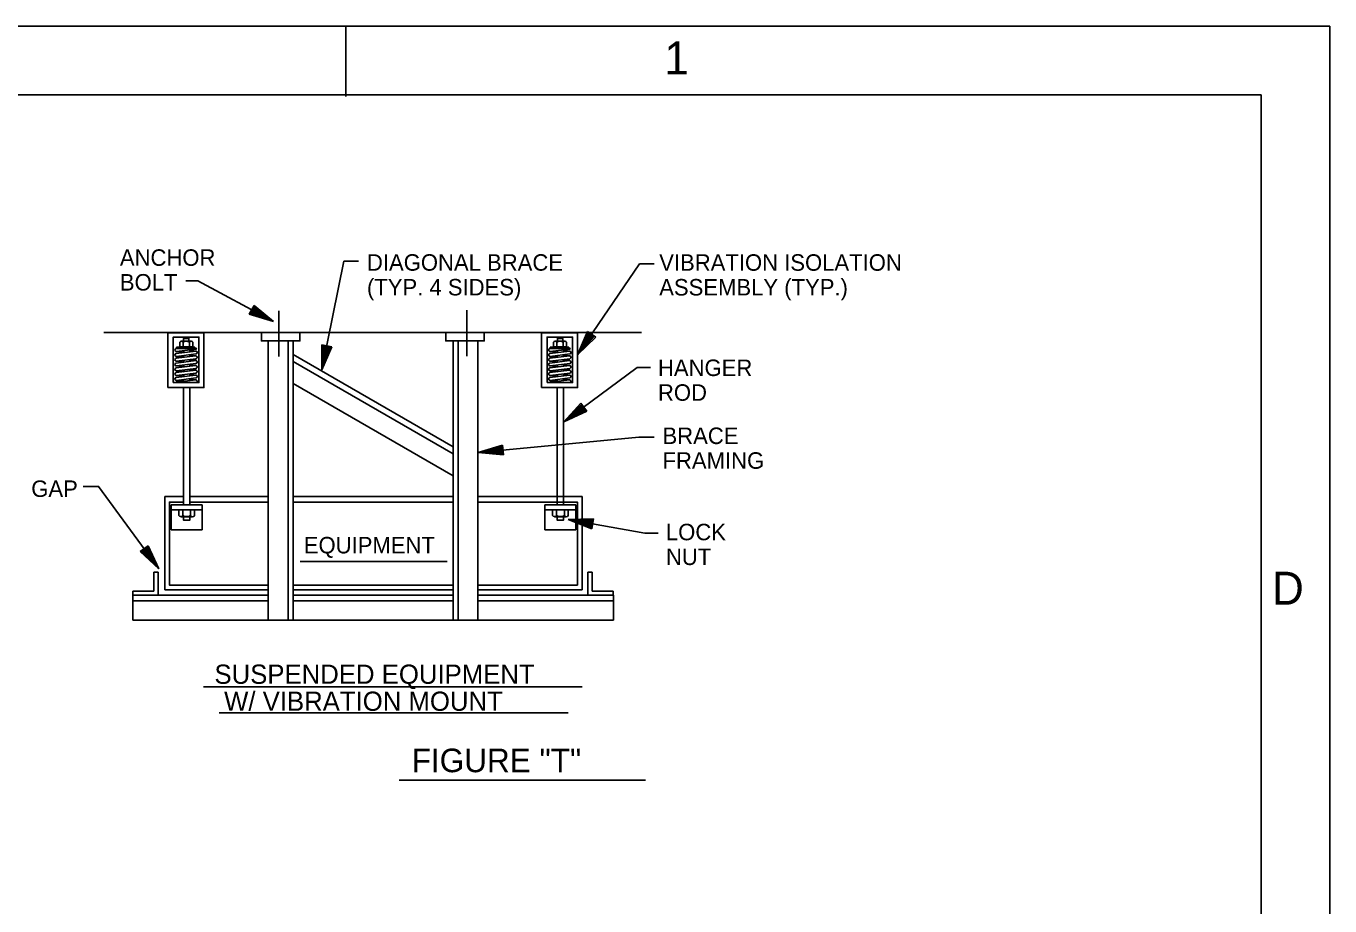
# Model space of a CAD drawing. Extents: x 10040.55 to 10045.84, y 10033.26 to 10035.76.
# Drawn here: x 10043.256 to 10044.047, y 10035.222 to 10035.756 of the extents above; entities that cross this region are included whole.
import ezdxf

# ---------------------------------------------------------------- set-up
doc = ezdxf.new("R2010")
doc.units = 0
doc.layers.add('Level 1', color=7, linetype='Continuous')
doc.layers.add('Level 2', color=7, linetype='Continuous')

msp = doc.modelspace()

# ---------------------------------------------------------------- linework, layer by layer
at = {"layer": 'Level 1'}
for p, q in [((10040.54697, 10035.75552), (10044.04697, 10035.75552)), ((10043.45014, 10035.75552), (10043.45014, 10035.71285)), ((10044.04697, 10035.75552), (10044.04697, 10033.25552)), ((10040.71364, 10035.71385), (10044.0053, 10035.71385)), ((10044.0053, 10035.71385), (10044.0053, 10033.29719))]:
    msp.add_line(p, q, dxfattribs=at)
at = {"layer": 'Level 2'}
for p, q in [((10043.39166, 10035.5808), (10043.39453, 10035.5861)), ((10043.40633, 10035.5763), (10043.39202, 10035.58148)), ((10043.40633, 10035.5763), (10043.39241, 10035.58223)), ((10043.40633, 10035.5763), (10043.39274, 10035.58281)), ((10043.39306, 10035.58344), (10043.40633, 10035.5763)), ((10043.40633, 10035.5763), (10043.39343, 10035.58409)), ((10043.40633, 10035.5763), (10043.39377, 10035.58476)), ((10043.40633, 10035.5763), (10043.39413, 10035.58539)), ((10043.39453, 10035.5861), (10043.40633, 10035.5763)), ((10043.40955, 10035.55517), (10043.40955, 10035.58292)), ((10043.52365, 10035.55543), (10043.52365, 10035.58318)), ((10043.39166, 10035.5808), (10043.40633, 10035.5763)), ((10043.3035, 10035.5696), (10043.62956, 10035.5696)), ((10043.59674, 10035.57034), (10043.59074, 10035.55622)), ((10043.59074, 10035.55622), (10043.59738, 10035.56992)), ((10043.59074, 10035.55622), (10043.59808, 10035.56946)), ((10043.59074, 10035.55622), (10043.59863, 10035.56906)), ((10043.59921, 10035.56868), (10043.59074, 10035.55622)), ((10043.59074, 10035.55622), (10043.59983, 10035.56824)), ((10043.59074, 10035.55622), (10043.60045, 10035.56783)), ((10043.59074, 10035.55622), (10043.60104, 10035.56742)), ((10043.60172, 10035.56694), (10043.59074, 10035.55622)), ((10043.59674, 10035.57034), (10043.60172, 10035.56694)), ((10043.3473, 10035.55992), (10043.35985, 10035.55992)), ((10043.35192, 10035.55756), (10043.3473, 10035.55814)), ((10043.34731, 10035.557), (10043.35915, 10035.55846)), ((10043.34748, 10035.55814), (10043.35931, 10035.55958)), ((10043.35873, 10035.56074), (10043.34754, 10035.56074)), ((10043.34754, 10035.56074), (10043.34754, 10035.55992)), ((10043.3495, 10035.56109), (10043.3495, 10035.56384)), ((10043.3495, 10035.56109), (10043.3574, 10035.56109)), ((10043.35049, 10035.56444), (10043.35641, 10035.56444)), ((10043.35146, 10035.56109), (10043.35146, 10035.56384)), ((10043.3517, 10035.55866), (10043.3517, 10035.55755)), ((10043.35543, 10035.56109), (10043.35543, 10035.56384)), ((10043.35563, 10035.55914), (10043.35563, 10035.55801)), ((10043.35563, 10035.55891), (10043.35923, 10035.55847)), ((10043.3574, 10035.56109), (10043.3574, 10035.56382)), ((10043.35873, 10035.56074), (10043.35873, 10035.55992)), ((10043.40316, 10035.39529), (10043.40316, 10035.56457)), ((10043.41522, 10035.56457), (10043.41522, 10035.39529)), ((10043.41826, 10035.39529), (10043.41826, 10035.56457)), ((10043.43575, 10035.5623), (10043.4357, 10035.54695)), ((10043.4357, 10035.54695), (10043.4365, 10035.56215)), ((10043.4357, 10035.54695), (10043.43733, 10035.562)), ((10043.4357, 10035.54695), (10043.43799, 10035.56184)), ((10043.43868, 10035.56172), (10043.4357, 10035.54695)), ((10043.4357, 10035.54695), (10043.43942, 10035.56155)), ((10043.4357, 10035.54695), (10043.44015, 10035.56142)), ((10043.4357, 10035.54695), (10043.44085, 10035.56126)), ((10043.44166, 10035.56109), (10043.4357, 10035.54695)), ((10043.43575, 10035.5623), (10043.44166, 10035.56109)), ((10043.51526, 10035.56457), (10043.51526, 10035.39529)), ((10043.51829, 10035.39529), (10043.51829, 10035.56457)), ((10043.53035, 10035.56457), (10043.53035, 10035.39529)), ((10043.57395, 10035.55992), (10043.5865, 10035.55992)), ((10043.57856, 10035.55756), (10043.57395, 10035.55814)), ((10043.57396, 10035.557), (10043.58579, 10035.55846)), ((10043.57413, 10035.55814), (10043.58596, 10035.55958)), ((10043.58538, 10035.56074), (10043.57419, 10035.56074)), ((10043.57419, 10035.56074), (10043.57419, 10035.55992)), ((10043.57615, 10035.56109), (10043.57615, 10035.56384)), ((10043.57615, 10035.56109), (10043.58404, 10035.56109)), ((10043.57714, 10035.56444), (10043.58305, 10035.56444)), ((10043.5781, 10035.56109), (10043.5781, 10035.56384)), ((10043.57834, 10035.55866), (10043.57834, 10035.55755)), ((10043.58207, 10035.56109), (10043.58207, 10035.56384)), ((10043.58227, 10035.55914), (10043.58227, 10035.55801)), ((10043.58227, 10035.55891), (10043.58588, 10035.55847)), ((10043.58404, 10035.56109), (10043.58404, 10035.56382)), ((10043.58538, 10035.56074), (10043.58538, 10035.55992)), ((10043.3473, 10035.55409), (10043.35914, 10035.55554)), ((10043.35192, 10035.55174), (10043.3473, 10035.55231)), ((10043.34731, 10035.55119), (10043.35915, 10035.55263)), ((10043.35192, 10035.55467), (10043.34732, 10035.55521)), ((10043.34748, 10035.55232), (10043.35931, 10035.55376)), ((10043.34749, 10035.55522), (10043.35932, 10035.55668)), ((10043.34749, 10035.54941), (10043.35932, 10035.55085)), ((10043.3517, 10035.55575), (10043.3517, 10035.55463)), ((10043.3517, 10035.55285), (10043.3517, 10035.55173)), ((10043.3517, 10035.54996), (10043.3517, 10035.5488)), ((10043.35563, 10035.55627), (10043.35563, 10035.55515)), ((10043.35933, 10035.55554), (10043.35563, 10035.556)), ((10043.35563, 10035.55334), (10043.35563, 10035.55218)), ((10043.35931, 10035.55263), (10043.35563, 10035.55308)), ((10043.35563, 10035.55041), (10043.35563, 10035.54928)), ((10043.35933, 10035.54972), (10043.35563, 10035.55018)), ((10043.51526, 10035.50028), (10043.41826, 10035.55628)), ((10043.41826, 10035.55219), (10043.51526, 10035.49619)), ((10043.57395, 10035.55409), (10043.58578, 10035.55554)), ((10043.57856, 10035.55174), (10043.57395, 10035.55231)), ((10043.57396, 10035.55119), (10043.58579, 10035.55263)), ((10043.57856, 10035.55467), (10043.57397, 10035.55521)), ((10043.57413, 10035.55232), (10043.58596, 10035.55376)), ((10043.57414, 10035.55522), (10043.58597, 10035.55668)), ((10043.57414, 10035.54941), (10043.58597, 10035.55085)), ((10043.57834, 10035.55575), (10043.57834, 10035.55463)), ((10043.57834, 10035.55285), (10043.57834, 10035.55173)), ((10043.57834, 10035.54996), (10043.57834, 10035.5488)), ((10043.58227, 10035.55627), (10043.58227, 10035.55515)), ((10043.58598, 10035.55554), (10043.58227, 10035.556)), ((10043.58227, 10035.55334), (10043.58227, 10035.55218)), ((10043.58596, 10035.55263), (10043.58227, 10035.55308)), ((10043.58227, 10035.55041), (10043.58227, 10035.54928)), ((10043.58598, 10035.54972), (10043.58227, 10035.55018)), ((10043.3473, 10035.54827), (10043.35914, 10035.54972)), ((10043.35192, 10035.54592), (10043.3473, 10035.54648)), ((10043.3473, 10035.54245), (10043.35914, 10035.54389)), ((10043.34731, 10035.54535), (10043.35915, 10035.5468)), ((10043.35192, 10035.54883), (10043.34732, 10035.5494)), ((10043.35192, 10035.54301), (10043.34732, 10035.54357)), ((10043.34748, 10035.54649), (10043.35931, 10035.54794)), ((10043.34748, 10035.54067), (10043.35931, 10035.5421)), ((10043.34749, 10035.54358), (10043.35932, 10035.54503)), ((10043.3517, 10035.54706), (10043.3517, 10035.54591)), ((10043.3517, 10035.54414), (10043.3517, 10035.543)), ((10043.35563, 10035.54751), (10043.35563, 10035.54639)), ((10043.35931, 10035.5468), (10043.35563, 10035.54726)), ((10043.35563, 10035.54458), (10043.35563, 10035.54346)), ((10043.35933, 10035.54389), (10043.35563, 10035.54435)), ((10043.57395, 10035.54827), (10043.58578, 10035.54972)), ((10043.57856, 10035.54592), (10043.57395, 10035.54648)), ((10043.57395, 10035.54245), (10043.58578, 10035.54389)), ((10043.57396, 10035.54535), (10043.58579, 10035.5468)), ((10043.57856, 10035.54883), (10043.57397, 10035.5494)), ((10043.57856, 10035.54301), (10043.57397, 10035.54357)), ((10043.57413, 10035.54649), (10043.58596, 10035.54794)), ((10043.57413, 10035.54067), (10043.58596, 10035.5421)), ((10043.57414, 10035.54358), (10043.58597, 10035.54503)), ((10043.57834, 10035.54706), (10043.57834, 10035.54591)), ((10043.57834, 10035.54414), (10043.57834, 10035.543)), ((10043.58227, 10035.54751), (10043.58227, 10035.54639)), ((10043.58596, 10035.5468), (10043.58227, 10035.54726)), ((10043.58227, 10035.54458), (10043.58227, 10035.54346)), ((10043.58598, 10035.54389), (10043.58227, 10035.54435)), ((10043.3457, 10035.53933), (10043.35915, 10035.54098)), ((10043.35192, 10035.54009), (10043.3473, 10035.54066)), ((10043.3517, 10035.5412), (10043.3517, 10035.54004)), ((10043.3517, 10035.53631), (10043.3517, 10035.4652)), ((10043.35563, 10035.54169), (10043.35563, 10035.54053)), ((10043.35931, 10035.54098), (10043.35563, 10035.54143)), ((10043.35563, 10035.53624), (10043.35563, 10035.4652)), ((10043.51526, 10035.48284), (10043.41826, 10035.53884)), ((10043.57234, 10035.53933), (10043.58579, 10035.54098)), ((10043.57856, 10035.54009), (10043.57395, 10035.54066)), ((10043.57834, 10035.5412), (10043.57834, 10035.54004)), ((10043.57834, 10035.53631), (10043.57834, 10035.4652)), ((10043.58227, 10035.54169), (10043.58227, 10035.54053)), ((10043.58596, 10035.54098), (10043.58227, 10035.54143)), ((10043.58227, 10035.53624), (10043.58227, 10035.4652)), ((10043.59278, 10035.52692), (10043.5825, 10035.51552)), ((10043.5825, 10035.51552), (10043.59324, 10035.5263)), ((10043.59278, 10035.52692), (10043.59638, 10035.52207)), ((10043.5825, 10035.51552), (10043.59376, 10035.52564)), ((10043.5825, 10035.51552), (10043.59415, 10035.52509)), ((10043.59457, 10035.52453), (10043.5825, 10035.51552)), ((10043.5825, 10035.51552), (10043.59502, 10035.52392)), ((10043.5825, 10035.51552), (10043.59547, 10035.52333)), ((10043.5825, 10035.51552), (10043.5959, 10035.52274)), ((10043.59638, 10035.52207), (10043.5825, 10035.51552)), ((10043.54517, 10035.5014), (10043.53047, 10035.49698)), ((10043.53047, 10035.49698), (10043.54524, 10035.50064)), ((10043.53047, 10035.49698), (10043.54534, 10035.49979)), ((10043.53047, 10035.49698), (10043.54539, 10035.49913)), ((10043.54547, 10035.49843), (10043.53047, 10035.49698)), ((10043.53047, 10035.49698), (10043.54552, 10035.49768)), ((10043.54573, 10035.4954), (10043.53047, 10035.49698)), ((10043.53047, 10035.49698), (10043.5456, 10035.49694)), ((10043.53047, 10035.49698), (10043.54567, 10035.49621)), ((10043.54517, 10035.5014), (10043.54573, 10035.4954)), ((10043.34047, 10035.47021), (10043.34047, 10035.41369)), ((10043.35164, 10035.47021), (10043.34047, 10035.47021)), ((10043.34424, 10035.46519), (10043.36299, 10035.46519)), ((10043.34424, 10035.44998), (10043.34424, 10035.46519)), ((10043.40316, 10035.47021), (10043.35554, 10035.47021)), ((10043.36299, 10035.46519), (10043.36299, 10035.44998)), ((10043.51526, 10035.47021), (10043.41826, 10035.47021)), ((10043.51526, 10035.46685), (10043.41826, 10035.46685)), ((10043.59343, 10035.47021), (10043.53035, 10035.47021)), ((10043.57828, 10035.47021), (10043.56711, 10035.47021)), ((10043.57089, 10035.46519), (10043.58964, 10035.46519)), ((10043.57089, 10035.44998), (10043.57089, 10035.46519)), ((10043.58964, 10035.46519), (10043.58964, 10035.44998)), ((10043.59343, 10035.41369), (10043.59343, 10035.47021)), ((10043.36299, 10035.46219), (10043.34424, 10035.46219)), ((10043.35845, 10035.46206), (10043.3489, 10035.46206)), ((10043.3489, 10035.46206), (10043.3489, 10035.45875)), ((10043.35725, 10035.458), (10043.35008, 10035.458)), ((10043.35128, 10035.46206), (10043.35128, 10035.45873)), ((10043.35608, 10035.46206), (10043.35608, 10035.45873)), ((10043.35845, 10035.46206), (10043.35845, 10035.45873)), ((10043.58964, 10035.46219), (10043.57089, 10035.46219)), ((10043.58509, 10035.46206), (10043.57554, 10035.46206)), ((10043.57554, 10035.46206), (10043.57554, 10035.45875)), ((10043.5839, 10035.458), (10043.57673, 10035.458)), ((10043.57793, 10035.46206), (10043.57793, 10035.45873)), ((10043.58273, 10035.46206), (10043.58273, 10035.45873)), ((10043.60042, 10035.4566), (10043.58507, 10035.45628)), ((10043.59991, 10035.45367), (10043.58507, 10035.45628)), ((10043.59935, 10035.45067), (10043.58507, 10035.45628)), ((10043.58507, 10035.45628), (10043.59965, 10035.45219)), ((10043.58507, 10035.45628), (10043.60016, 10035.45501)), ((10043.58507, 10035.45628), (10043.59951, 10035.45148)), ((10043.58507, 10035.45628), (10043.59977, 10035.45293)), ((10043.58507, 10035.45628), (10043.60002, 10035.45436)), ((10043.58507, 10035.45628), (10043.60029, 10035.45584)), ((10043.58509, 10035.46206), (10043.58509, 10035.45873)), ((10043.60042, 10035.4566), (10043.59935, 10035.45067)), ((10043.36299, 10035.44998), (10043.34424, 10035.44998)), ((10043.58964, 10035.44998), (10043.57089, 10035.44998)), ((10043.32548, 10035.43678), (10043.33034, 10035.44033)), ((10043.33679, 10035.42641), (10043.32908, 10035.43944)), ((10043.33679, 10035.42641), (10043.32968, 10035.43985)), ((10043.33034, 10035.44033), (10043.33679, 10035.42641)), ((10043.32548, 10035.43678), (10043.33679, 10035.42641)), ((10043.33679, 10035.42641), (10043.32609, 10035.43724)), ((10043.33679, 10035.42641), (10043.32676, 10035.43775)), ((10043.33679, 10035.42641), (10043.32731, 10035.43813)), ((10043.32788, 10035.43855), (10043.33679, 10035.42641)), ((10043.33679, 10035.42641), (10043.32849, 10035.43899)), ((10043.33386, 10035.41283), (10043.33386, 10035.42441)), ((10043.33386, 10035.42441), (10043.33646, 10035.42441)), ((10043.33646, 10035.42441), (10043.33646, 10035.41044)), ((10043.42243, 10035.43072), (10043.51173, 10035.43072)), ((10043.59961, 10035.4244), (10043.59701, 10035.4244)), ((10043.59701, 10035.4244), (10043.59701, 10035.41042)), ((10043.59961, 10035.41281), (10043.59961, 10035.4244)), ((10043.41826, 10035.41648), (10043.51526, 10035.41648)), ((10043.32107, 10035.41039), (10043.32107, 10035.41283)), ((10043.32107, 10035.41283), (10043.33386, 10035.41283)), ((10043.40316, 10035.41039), (10043.32107, 10035.41039)), ((10043.32107, 10035.39529), (10043.32107, 10035.41039)), ((10043.34047, 10035.41369), (10043.40316, 10035.41369)), ((10043.41826, 10035.41369), (10043.51526, 10035.41369)), ((10043.51526, 10035.41039), (10043.41827, 10035.41039)), ((10043.53034, 10035.41039), (10043.61244, 10035.41039)), ((10043.53035, 10035.41369), (10043.59343, 10035.41369)), ((10043.61241, 10035.41281), (10043.59961, 10035.41281)), ((10043.61241, 10035.41036), (10043.61241, 10035.41281)), ((10043.61244, 10035.39529), (10043.61244, 10035.41039)), ((10043.32107, 10035.40705), (10043.40319, 10035.40705)), ((10043.41822, 10035.40705), (10043.51519, 10035.40705)), ((10043.53032, 10035.40705), (10043.61244, 10035.40705)), ((10043.61244, 10035.39529), (10043.32107, 10035.39529)), ((10043.36384, 10035.35475), (10043.59352, 10035.35475)), ((10043.3734, 10035.339), (10043.58493, 10035.339)), ((10043.48249, 10035.29829), (10043.63195, 10035.29829))]:
    msp.add_line(p, q, dxfattribs=at)
for points in [[(10043.45784, 10035.61288), (10043.44908, 10035.61288), (10043.4357, 10035.54695)], [(10043.6371, 10035.61133), (10043.62834, 10035.61133), (10043.59074, 10035.55622)], [(10043.35327, 10035.60103), (10043.36049, 10035.60103), (10043.40633, 10035.5763)], [(10043.35507, 10035.56446), (10043.35507, 10035.56611), (10043.35183, 10035.56611), (10043.35183, 10035.56446)], [(10043.39904, 10035.5696), (10043.39904, 10035.56457), (10043.42238, 10035.56457), (10043.42238, 10035.5696)], [(10043.51082, 10035.5696), (10043.51082, 10035.56457), (10043.53416, 10035.56457), (10043.53416, 10035.5696)], [(10043.58172, 10035.56446), (10043.58172, 10035.56611), (10043.57848, 10035.56611), (10043.57848, 10035.56446)], [(10043.63504, 10035.54849), (10043.6268, 10035.54849), (10043.5825, 10035.51552)], [(10043.6371, 10035.50625), (10043.62783, 10035.50625), (10043.53047, 10035.49698)], [(10043.29095, 10035.47638), (10043.30022, 10035.47638), (10043.33679, 10035.42641)], [(10043.35164, 10035.46685), (10043.34326, 10035.46685), (10043.34326, 10035.41648), (10043.40316, 10035.41648)], [(10043.40316, 10035.46685), (10043.35554, 10035.46685)], [(10043.53035, 10035.41648), (10043.59063, 10035.41648), (10043.59063, 10035.46685), (10043.53035, 10035.46685)], [(10043.3517, 10035.45798), (10043.3517, 10035.45598), (10043.35563, 10035.45598), (10043.35563, 10035.45798)], [(10043.57834, 10035.45798), (10043.57834, 10035.45598), (10043.58227, 10035.45598), (10043.58227, 10035.45798)], [(10043.63968, 10035.44804), (10043.63144, 10035.44804), (10043.58507, 10035.45628)]]:
    msp.add_lwpolyline(points, dxfattribs=at)
for points in [[(10043.3423, 10035.53631), (10043.36411, 10035.53631), (10043.36411, 10035.5695), (10043.3423, 10035.5695)], [(10043.34555, 10035.53933), (10043.3611, 10035.53933), (10043.3611, 10035.56695), (10043.34555, 10035.56695)], [(10043.56895, 10035.53631), (10043.59076, 10035.53631), (10043.59076, 10035.5695), (10043.56895, 10035.5695)], [(10043.5722, 10035.53933), (10043.58775, 10035.53933), (10043.58775, 10035.56695), (10043.5722, 10035.56695)]]:
    msp.add_lwpolyline(points, close=True, dxfattribs=at)
for centre, radius, start, end in [((10043.35048, 10035.56334), 0.0011, 27.8877, 152.03419), ((10043.35344, 10035.56079), 0.00365, 57.00616, 122.94298), ((10043.3564, 10035.56333), 0.0011, 26.78269, 151.8391), ((10043.57713, 10035.56334), 0.0011, 27.8877, 152.03419), ((10043.58009, 10035.56079), 0.00365, 57.00616, 122.94298), ((10043.58305, 10035.56333), 0.0011, 26.78269, 151.8391), ((10043.35009, 10035.45935), 0.00134, 206.78269, 331.8391), ((10043.35368, 10035.46242), 0.00441, 237.00616, 302.94298), ((10043.35726, 10035.45934), 0.00134, 207.8877, 332.03419), ((10043.57674, 10035.45935), 0.00134, 206.78269, 331.8391), ((10043.58032, 10035.46242), 0.00441, 237.00616, 302.94298), ((10043.5839, 10035.45934), 0.00134, 207.8877, 332.03419)]:
    msp.add_arc(centre, radius, start, end, dxfattribs=at)
for centre, major_axis, start_param, end_param in [((10043.34739, 10035.55902), (0, -0.000894), 3.251722, 6.393315), ((10043.35923, 10035.55756), (0, 0.000894), 3.251722, 6.393315), ((10043.35922, 10035.56047), (0, 0.000894), 3.251722, 4.030489), ((10043.57404, 10035.55902), (0, -0.000894), 3.251722, 6.393315), ((10043.58588, 10035.55756), (0, 0.000894), 3.251722, 6.393315), ((10043.58586, 10035.56047), (0, 0.000894), 3.251722, 4.030489), ((10043.34739, 10035.5532), (0, -0.000894), 3.251722, 6.393315), ((10043.3474, 10035.55611), (0, -0.000894), 3.251722, 6.393315), ((10043.3474, 10035.55029), (0, -0.000894), 3.251722, 6.393315), ((10043.35922, 10035.55465), (0, 0.000894), 3.251722, 6.393315), ((10043.35922, 10035.54883), (0, 0.000894), 3.251722, 6.393315), ((10043.35923, 10035.55174), (0, 0.000894), 3.251722, 6.393315), ((10043.57404, 10035.5532), (0, -0.000894), 3.251722, 6.393315), ((10043.57405, 10035.55611), (0, -0.000894), 3.251722, 6.393315), ((10043.57405, 10035.55029), (0, -0.000894), 3.251722, 6.393315), ((10043.58586, 10035.55465), (0, 0.000894), 3.251722, 6.393315), ((10043.58586, 10035.54883), (0, 0.000894), 3.251722, 6.393315), ((10043.58588, 10035.55174), (0, 0.000894), 3.251722, 6.393315), ((10043.34739, 10035.54737), (0, -0.000894), 3.251722, 6.393315), ((10043.34739, 10035.54155), (0, -0.000894), 3.251722, 6.393315), ((10043.3474, 10035.54446), (0, -0.000894), 3.251722, 6.393315), ((10043.35922, 10035.54301), (0, 0.000894), 3.251722, 6.393315), ((10043.35923, 10035.54592), (0, 0.000894), 3.251722, 6.393315), ((10043.57404, 10035.54737), (0, -0.000894), 3.251722, 6.393315), ((10043.57404, 10035.54155), (0, -0.000894), 3.251722, 6.393315), ((10043.57405, 10035.54446), (0, -0.000894), 3.251722, 6.393315), ((10043.58586, 10035.54301), (0, 0.000894), 3.251722, 6.393315), ((10043.58588, 10035.54592), (0, 0.000894), 3.251722, 6.393315), ((10043.35923, 10035.54009), (0, 0.000894), 3.693893, 6.387949), ((10043.58588, 10035.54009), (0, 0.000894), 3.693893, 6.387949)]:
    msp.add_ellipse(centre, major_axis=major_axis, ratio=0.9, start_param=start_param, end_param=end_param, dxfattribs=at)

# ---------------------------------------------------------------- texts
at = {"layer": 'Level 1'}
for s, p in [('1', (10043.64339, 10035.72619)), ('D', (10044.01182, 10035.40461))]:
    msp.add_text(s, height=0.02, dxfattribs=at).set_placement(p)
at = {"layer": 'Level 2'}
for s, height, p in [('ANCHOR', 0.01, (10043.31318, 10035.61013)), ('DIAGONAL BRACE', 0.01, (10043.46301, 10035.60717)), ('VIBRATION ISOLATION', 0.01, (10043.64024, 10035.60713)), ('BOLT', 0.01, (10043.31318, 10035.59513)), ('(TYP. 4 SIDES)', 0.01, (10043.46301, 10035.59217)), ('ASSEMBLY (TYP.)', 0.01, (10043.64024, 10035.59213)), ('HANGER', 0.01, (10043.63949, 10035.54328)), ('ROD', 0.01, (10043.63949, 10035.52828)), ('BRACE', 0.01, (10043.64224, 10035.50206)), ('FRAMING', 0.01, (10043.64224, 10035.48706)), ('GAP', 0.01, (10043.25944, 10035.46997)), ('LOCK', 0.01, (10043.6443, 10035.44368)), ('EQUIPMENT', 0.01, (10043.42472, 10035.43572)), ('NUT', 0.01, (10043.6443, 10035.42868)), ('SUSPENDED EQUIPMENT', 0.0116667, (10043.37053, 10035.35663)), ('W/ VIBRATION MOUNT', 0.0116667, (10043.37638, 10035.34025)), ('FIGURE "T"', 0.014301, (10043.49011, 10035.30303))]:
    msp.add_text(s, height=height, dxfattribs=at).set_placement(p)

doc.saveas('drawing.dxf')
